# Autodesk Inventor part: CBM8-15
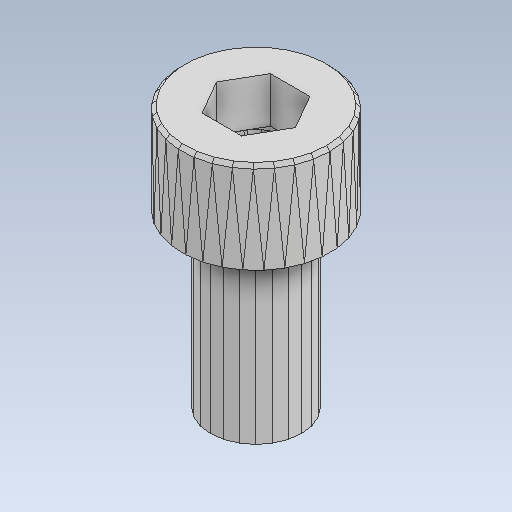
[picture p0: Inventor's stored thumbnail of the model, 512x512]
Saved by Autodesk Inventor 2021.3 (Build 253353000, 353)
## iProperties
Created: 2022-02
Part Number: CBM8-15
Material: 一般
Document SubType Name: Modeling
Designer: kengo
Density: 1 g/cm^3
Appearance: 既定
Author: kengo
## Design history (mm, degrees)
feature "CBM8-15"
node "ソリッド1"
